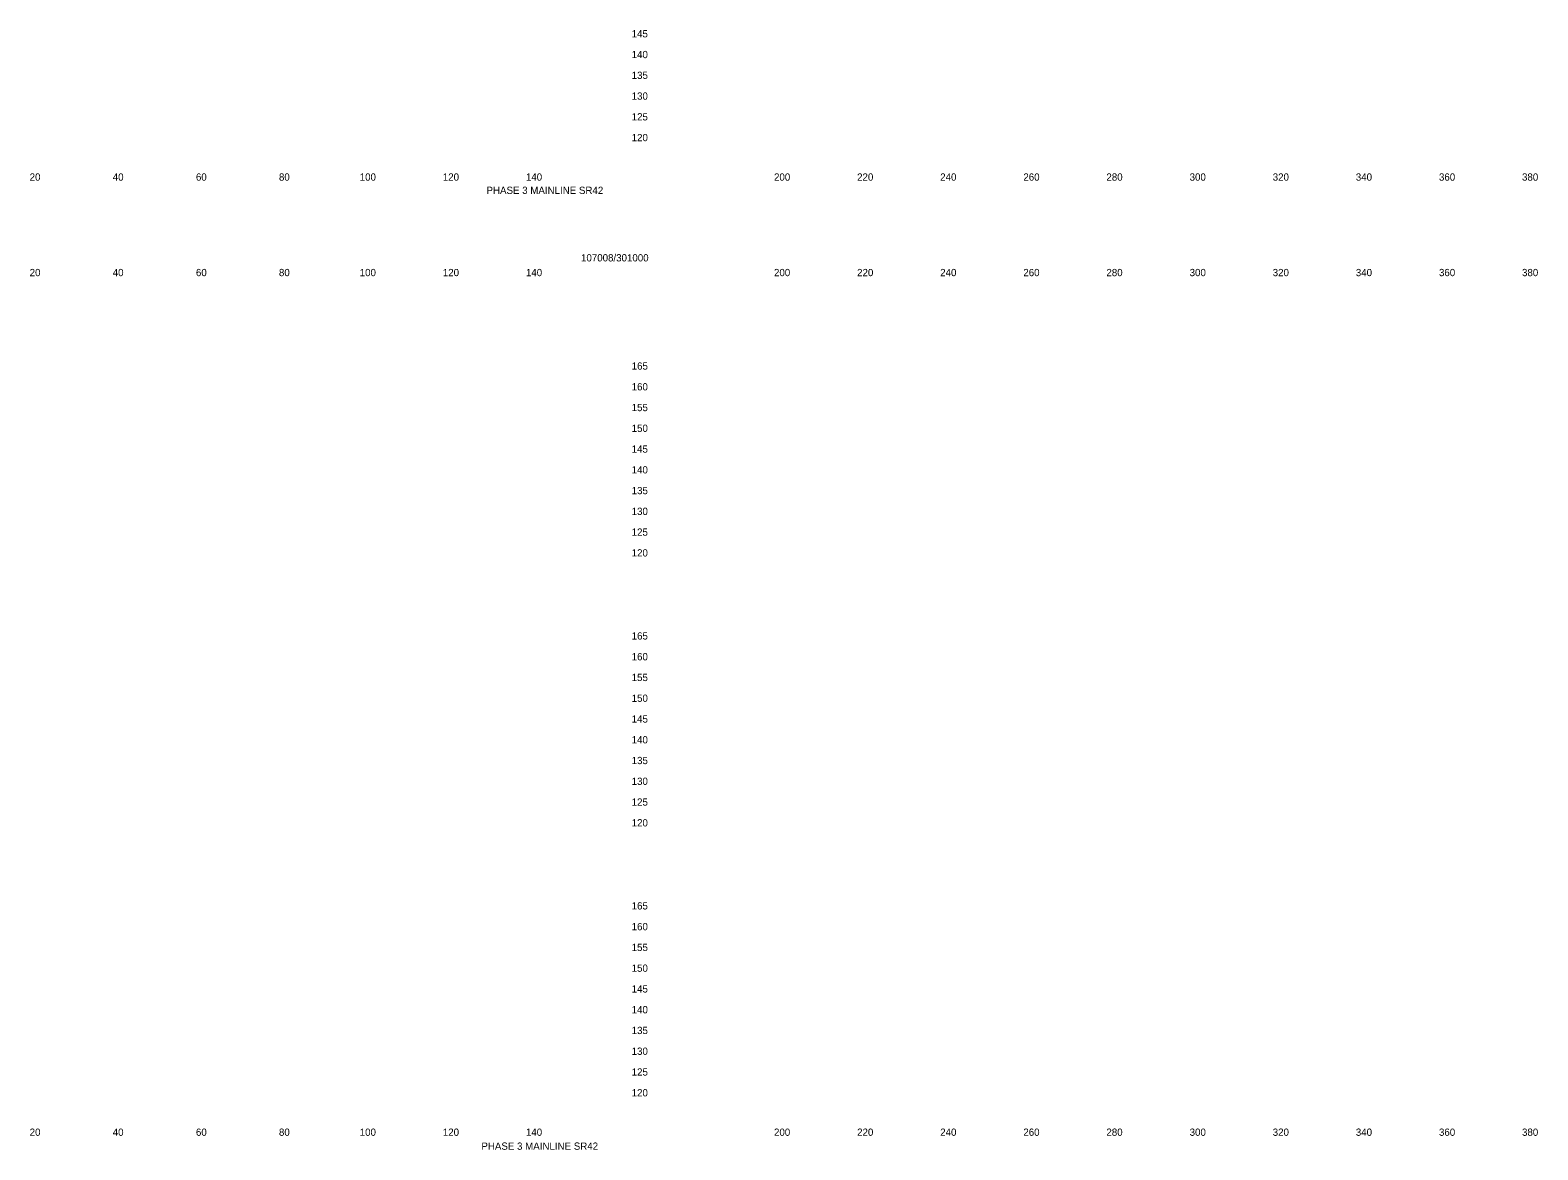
# Model space of a CAD drawing. Extents: x 21281 to 22024, y 6472 to 15198.
# Drawn here: x 21661.4 to 22024.2, y 6472 to 6741.6 of the extents above; entities that cross this region are included whole.
import ezdxf

# ---------------------------------------------------------------- set-up
doc = ezdxf.new("R2010")
doc.units = 0
doc.layers.add('Draft_XS_Grid', color=7, linetype='Continuous')
doc.layers.add('Draft_XS_Text', color=7, linetype='Continuous')

msp = doc.modelspace()

# ---------------------------------------------------------------- texts
at = {"layer": 'Draft_XS_Grid'}
for s, p in [('  145  ', (21804.84, 6739.84)), ('  140  ', (21804.84, 6734.84)), ('  135  ', (21804.84, 6729.84)), ('  130  ', (21804.84, 6724.84)), ('  125  ', (21804.84, 6719.84)), ('  120  ', (21804.84, 6714.84)), ('  165  ', (21804.84, 6659.84)), ('  160  ', (21804.84, 6654.84)), ('  155  ', (21804.84, 6649.84)), ('  150  ', (21804.84, 6644.84)), ('  145  ', (21804.84, 6639.84)), ('  140  ', (21804.84, 6634.84)), ('  135  ', (21804.84, 6629.84)), ('  130  ', (21804.84, 6624.84)), ('  125  ', (21804.84, 6619.84)), ('  120  ', (21804.84, 6614.84)), ('  165  ', (21804.84, 6594.84)), ('  160  ', (21804.84, 6589.84)), ('  155  ', (21804.84, 6584.84)), ('  150  ', (21804.84, 6579.84)), ('  145  ', (21804.84, 6574.84)), ('  140  ', (21804.84, 6569.84)), ('  135  ', (21804.84, 6564.84)), ('  130  ', (21804.84, 6559.84)), ('  125  ', (21804.84, 6554.84)), ('  120  ', (21804.84, 6549.84)), ('  165  ', (21804.84, 6529.84)), ('  160  ', (21804.84, 6524.84)), ('  155  ', (21804.84, 6519.84)), ('  150  ', (21804.84, 6514.84)), ('  145  ', (21804.84, 6509.84)), ('  140  ', (21804.84, 6504.84)), ('  135  ', (21804.84, 6499.84)), ('  130  ', (21804.84, 6494.84)), ('  125  ', (21804.84, 6489.84)), ('  120  ', (21804.84, 6484.84))]:
    msp.add_text(s, height=1.75, dxfattribs=at).set_placement(p)
at = {"layer": 'Draft_XS_Text'}
for s, p in [('  20  ', (21659.95, 6705.34)), ('  40  ', (21679.95, 6705.34)), ('  60  ', (21699.97, 6705.34)), ('  80  ', (21719.95, 6705.34)), ('  100  ', (21739.39, 6705.34)), ('  120  ', (21759.39, 6705.34)), ('  140  ', (21779.39, 6705.34)), ('  200  ', (21839.1, 6705.34)), ('  220  ', (21859.1, 6705.34)), ('  240  ', (21879.1, 6705.34)), ('  260  ', (21899.11, 6705.34)), ('  280  ', (21919.1, 6705.34)), ('  300  ', (21939.13, 6705.34)), ('  320  ', (21959.13, 6705.34)), ('  340  ', (21979.13, 6705.34)), ('  360  ', (21999.14, 6705.34)), ('  380  ', (22019.13, 6705.34)), ('PHASE 3 MAINLINE SR42', (21771.21, 6702.14)), ('107008/301000', (21793.95, 6685.89)), ('  20  ', (21659.95, 6682.34)), ('  40  ', (21679.95, 6682.34)), ('  60  ', (21699.97, 6682.34)), ('  80  ', (21719.95, 6682.34)), ('  100  ', (21739.39, 6682.34)), ('  120  ', (21759.39, 6682.34)), ('  140  ', (21779.39, 6682.34)), ('  200  ', (21839.1, 6682.34)), ('  220  ', (21859.1, 6682.34)), ('  240  ', (21879.1, 6682.34)), ('  260  ', (21899.11, 6682.34)), ('  280  ', (21919.1, 6682.34)), ('  300  ', (21939.13, 6682.34)), ('  320  ', (21959.13, 6682.34)), ('  340  ', (21979.13, 6682.34)), ('  360  ', (21999.14, 6682.34)), ('  380  ', (22019.13, 6682.34)), ('  20  ', (21659.95, 6475.34)), ('  40  ', (21679.95, 6475.34)), ('  60  ', (21699.97, 6475.34)), ('  80  ', (21719.95, 6475.34)), ('  100  ', (21739.39, 6475.34)), ('  120  ', (21759.39, 6475.34)), ('PHASE 3 MAINLINE SR42', (21769.97, 6471.98)), ('  140  ', (21779.39, 6475.34)), ('  200  ', (21839.1, 6475.34)), ('  220  ', (21859.1, 6475.34)), ('  240  ', (21879.1, 6475.34)), ('  260  ', (21899.11, 6475.34)), ('  280  ', (21919.1, 6475.34)), ('  300  ', (21939.13, 6475.34)), ('  320  ', (21959.13, 6475.34)), ('  340  ', (21979.13, 6475.34)), ('  360  ', (21999.14, 6475.34)), ('  380  ', (22019.13, 6475.34))]:
    msp.add_text(s, height=1.75, dxfattribs=at).set_placement(p)

doc.saveas('drawing.dxf')
